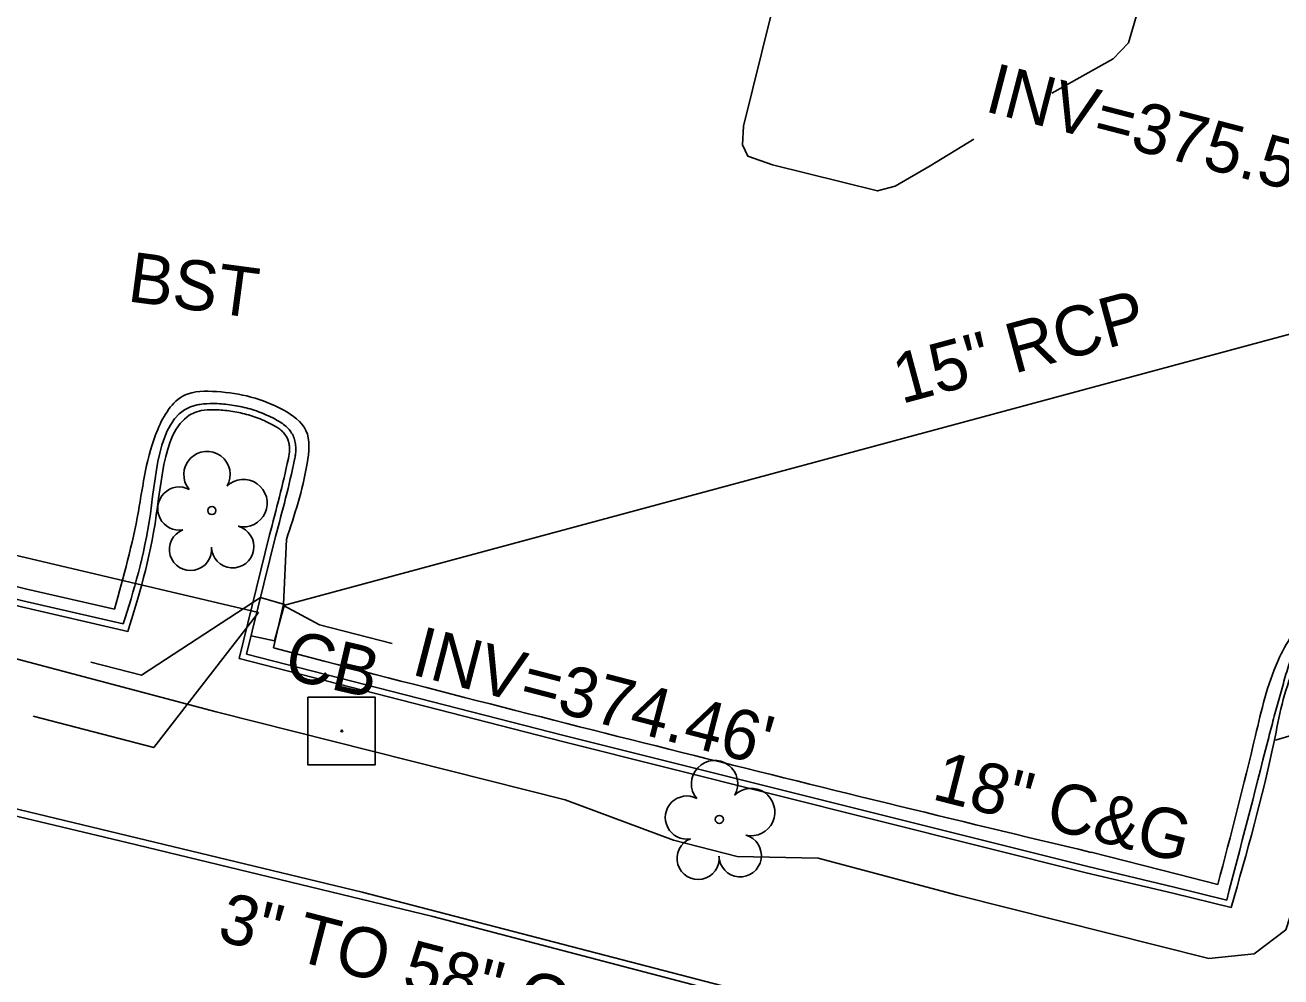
# Model space of a CAD drawing. Extents: x 2089016 to 2094354, y 862840 to 864725.
# Drawn here: x 2092662.4 to 2092763, y 863705 to 863781.3 of the extents above; entities that cross this region are included whole.
import ezdxf

# ---------------------------------------------------------------- set-up
doc = ezdxf.new("R2010")
doc.units = 0
for name, color, linetype in [('Exist Building', 7, 'Continuous'), ('Exist Building Text', 7, 'Continuous'), ('Exist Other Culture Fence Line', 7, 'Continuous'), ('Exist Roads Curbs', 7, 'Continuous'), ('Exist Roads Curbs Text', 7, 'Continuous'), ('Exist Roads EOP', 7, 'Continuous'), ('Exist Roads EOP Other', 7, 'Continuous'), ('Exist Roads EOP Other Text', 7, 'Continuous'), ('Exist Structure Minor Catch Basin Text', 7, 'Continuous'), ('Exist Structure Minor Drop Inlet', 7, 'Continuous'), ('Exist Structure Minor Drop Inlet Leader', 7, 'Continuous'), ('Exist Structure Minor Pipes RCP 15 Inch', 7, 'Continuous'), ('Exist Structure Minor Pipes RCP 15 Inch Invert', 7, 'Continuous'), ('Exist Structure Minor Pipes RCP 15 Inch Leader', 7, 'Continuous'), ('Exist Structure Minor Pipes RCP 15 Inch Text', 7, 'Continuous'), ('Exist Utilities Other Pole With Base CELL', 7, 'Continuous'), ('Exist Vegetation Hedge Row', 7, 'Continuous'), ('Exist Vegetation Tree CELL', 7, 'Continuous')]:
    doc.layers.add(name, color=color, linetype=linetype)

msp = doc.modelspace()

# ---------------------------------------------------------------- linework, layer by layer
at = {"layer": 'Exist Building'}
for p, q in [((2092670.55, 863715.8), (2092651.63, 863720.29)), ((2092695.06, 863709.86), (2092670.55, 863715.8)), ((2092719.12, 863703.57), (2092695.06, 863709.86))]:
    msp.add_line(p, q, dxfattribs=at)
at = {"layer": 'Exist Other Culture Fence Line'}
msp.add_lwpolyline([(2092811.78, 863734.58), (2092806.76, 863722.98), (2092803.58, 863716.36), (2092801.54, 863712.92), (2092798.77, 863709.38), (2092795.98, 863706.58), (2092790.64, 863701.95), (2092785.5, 863698.59), (2092780.3, 863696.17), (2092775.15, 863694.37), (2092768.83, 863693.52), (2092762.71, 863693.79), (2092750.99, 863695.98), (2092726.3, 863702.22), (2092689.4, 863711.81), (2092651.09, 863721.05), (2092618.36, 863728.9), (2092604.89, 863733.06), (2092585.02, 863756.31)], dxfattribs=at)
at = {"layer": 'Exist Roads Curbs'}
for p, q in [((2092679.54, 863730.55), (2092681.98, 863740.45)), ((2092680.15, 863730.91), (2092682.46, 863740.33)), ((2092705.57, 863724.38), (2092680.15, 863730.91)), ((2092705.45, 863723.89), (2092679.54, 863730.55)), ((2092747.43, 863713.38), (2092705.45, 863723.89)), ((2092747.55, 863713.87), (2092705.57, 863724.38)), ((2092754.49, 863712.21), (2092758.69, 863711.17))]:
    msp.add_line(p, q, dxfattribs=at)
for points in [[(2092744.69, 863775.86), (2092749.6, 863778.62), (2092750.83, 863779.91), (2092751.77, 863783.19), (2092756.78, 863802.38), (2092756.98, 863804.25), (2092756.46, 863805.43), (2092755.72, 863805.88), (2092742.47, 863809.01), (2092744.3, 863816.53)], [(2092722.89, 863785), (2092719.96, 863773.22), (2092719.89, 863771.71), (2092720.31, 863770.82), (2092722.3, 863770.11), (2092730.7, 863768.03), (2092732.12, 863768.41), (2092734.92, 863770.04), (2092738.43, 863772.18)], [(2092670.62, 863732.71), (2092662.11, 863734.68), (2092652.85, 863736.97)], [(2092670.26, 863733.32), (2092662.22, 863735.16), (2092652.97, 863737.45)], [(2092754.49, 863712.21), (2092747.55, 863713.87)], [(2092759.05, 863710.6), (2092754.37, 863711.73), (2092747.43, 863713.38)]]:
    msp.add_lwpolyline(points, dxfattribs=at)
for points in [[(2092682.46, 863740.33), (2092683.99, 863746.49), (2092684.06, 863746.88), (2092684.08, 863747.08), (2092684.09, 863747.28), (2092684.06, 863747.73), (2092683.95, 863748.21), (2092683.48, 863748.98), (2092683.11, 863749.31), (2092682.71, 863749.57), (2092681.41, 863750.21), (2092680.1, 863750.64), (2092678.79, 863750.89), (2092677.46, 863750.99), (2092676.43, 863750.92), (2092676.19, 863750.88), (2092672.43, 863742.15), (2092670.26, 863733.32)], [(2092681.98, 863740.45), (2092683.49, 863746.58), (2092683.59, 863747.3), (2092683.56, 863747.66), (2092683.48, 863748.02), (2092683.1, 863748.66), (2092682.81, 863748.92), (2092682.47, 863749.14), (2092681.22, 863749.75), (2092679.98, 863750.16), (2092678.72, 863750.4), (2092677.46, 863750.49), (2092676.51, 863750.42), (2092672.91, 863742.03), (2092670.62, 863732.71)], [(2092787.76, 863728.65), (2092779.29, 863730.7), (2092777.51, 863731.17), (2092775.74, 863731.64), (2092773.97, 863732.11), (2092772.2, 863732.58), (2092771.36, 863732.81), (2092770.53, 863733.05), (2092769.7, 863733.28), (2092768.87, 863733.51), (2092768.49, 863733.59), (2092768.11, 863733.62), (2092767.35, 863733.52), (2092766.58, 863733.26), (2092766.2, 863733.07), (2092766.01, 863732.95), (2092765.83, 863732.83), (2092765.45, 863732.56), (2092765.09, 863732.27), (2092764.76, 863731.94), (2092764.6, 863731.76), (2092764.45, 863731.58), (2092763.98, 863730.84), (2092763.67, 863730.04), (2092763.23, 863728.54), (2092762.81, 863727.04), (2092762.4, 863725.54), (2092762.01, 863724.03), (2092758.69, 863711.17)], [(2092788.12, 863728.07), (2092779.56, 863730.11), (2092772.07, 863732.1), (2092768.85, 863733), (2092766.11, 863732.39), (2092764.12, 863729.81), (2092762.49, 863723.9), (2092759.05, 863710.6)], [(2092530.07, 863721.03), (2092534.33, 863719.65), (2092575.6, 863708.21), (2092621.07, 863695.65), (2092662.26, 863684.12), (2092705.47, 863672.32)], [(2092530.34, 863721.46), (2092534.48, 863720.13), (2092575.73, 863708.69), (2092621.2, 863696.13), (2092662.4, 863684.6), (2092705.61, 863672.81)]]:
    msp.add_spline(points, degree=3, dxfattribs=at)
at = {"layer": 'Exist Roads EOP'}
for points in [[(2092682.29, 863731.41), (2092683.1, 863734.91), (2092683.33, 863740.1)], [(2092669.57, 863734.5), (2092662.54, 863736.11), (2092653.24, 863738.45)], [(2092757.98, 863712.44), (2092754.75, 863713.26), (2092747.83, 863715.02)]]:
    msp.add_lwpolyline(points, dxfattribs=at)
msp.add_ellipse((2093446.69, 866647.98), major_axis=(-2241.79, -2016.35), ratio=0.999899, start_param=0.582015, end_param=0.604423, dxfattribs=at)
for points in [[(2092351.39, 863867.42), (2092346.28, 863853.71), (2092340.44, 863838.83), (2092338.02, 863832.45), (2092326.59, 863809.54), (2092324.18, 863804.42), (2092322.34, 863798.11), (2092322.21, 863794.63), (2092323.26, 863788.18), (2092325.31, 863783.21), (2092329.49, 863777.7), (2092333.36, 863774.11), (2092338.14, 863771.94), (2092365.19, 863764.36), (2092404.76, 863753.49), (2092444.45, 863742.49), (2092470.82, 863735.23), (2092515.55, 863722.74), (2092529.36, 863718.89), (2092533.92, 863717.65), (2092575.11, 863706.35), (2092620.49, 863693.63), (2092661.52, 863682.27), (2092704.83, 863670.36)], [(2092683.33, 863740.1), (2092685, 863746.18), (2092684.9, 863748.83), (2092683.08, 863750.47), (2092677.74, 863751.94), (2092675.17, 863751.65), (2092673.02, 863748.9), (2092671.47, 863742.32), (2092669.57, 863734.5)], [(2092787.17, 863729.78), (2092780.94, 863731.2), (2092772.37, 863733.46), (2092769.24, 863734.33), (2092765.5, 863733.83), (2092762.81, 863730.4), (2092761, 863724.37), (2092757.98, 863712.44)], [(2092828.1, 863729.19), (2092826.25, 863724.52), (2092817.36, 863700.95), (2092813.46, 863691.03), (2092810.42, 863683.66), (2092808.15, 863679.13), (2092808.17, 863679.13), (2092804.47, 863673.86), (2092801.41, 863670.18), (2092796.05, 863666.12), (2092792.79, 863663.98), (2092786.45, 863660.55), (2092777.32, 863657), (2092767.89, 863655.43), (2092759.35, 863655.78), (2092746.24, 863658.87)], [(2092733.96, 863624.56), (2092729.42, 863627.24), (2092710.26, 863638.22), (2092685.56, 863646.14), (2092644.34, 863656.7), (2092636.3, 863658.85), (2092633.44, 863659.08), (2092631.45, 863657.89), (2092628.59, 863656.45), (2092626.77, 863655.79), (2092624.31, 863656.27), (2092613.98, 863659.23), (2092588.53, 863665.82), (2092584.48, 863666.74), (2092582.65, 863668.4), (2092580.87, 863671.65), (2092573.74, 863674.74), (2092530.78, 863685.35), (2092492.66, 863694.32), (2092471.57, 863699.61), (2092432.29, 863709.14), (2092390.23, 863719.97)]]:
    msp.add_spline(points, degree=3, dxfattribs=at)
at = {"layer": 'Exist Roads EOP Other'}
msp.add_lwpolyline([(2092806.46, 863743.02), (2092795.1, 863718.03), (2092770.9, 863724.24), (2092766.95, 863725.31), (2092762.59, 863724)], dxfattribs=at)
for points in [[(2092744.83, 863669.14), (2092739.53, 863670.51), (2092698.61, 863681.9), (2092655.56, 863693.83), (2092614.88, 863705.04), (2092572.51, 863716.82), (2092534.25, 863727.26), (2092490.85, 863739.3), (2092453.11, 863749.73), (2092413.17, 863760.74), (2092373.71, 863771.76), (2092342.37, 863780.54), (2092336.27, 863784.25), (2092333.6, 863789.3), (2092333.19, 863795.1), (2092333.89, 863798.65), (2092336.05, 863803.25), (2092354.66, 863838.72)], [(2092743.53, 863664.36), (2092738.18, 863665.86), (2092697.44, 863677.09), (2092654.51, 863689.14), (2092613.57, 863700.33), (2092571.3, 863712.05), (2092533.04, 863722.78), (2092489.78, 863734.76), (2092451.86, 863745.14), (2092412.17, 863756.14), (2092372.39, 863767.04), (2092340.78, 863775.86), (2092336.36, 863777.72), (2092332.77, 863780.97)], [(2092744.81, 863668.98), (2092750.12, 863667.66), (2092760.64, 863665.3), (2092769.92, 863665.38), (2092774.61, 863666.3), (2092783.29, 863669.98), (2092790.76, 863673.98), (2092797.37, 863680.05), (2092800.1, 863684.1), (2092802.17, 863688.67), (2092813.02, 863716.3)]]:
    msp.add_spline(points, degree=3, dxfattribs=at)
at = {"layer": 'Exist Structure Minor Drop Inlet'}
msp.add_lwpolyline([(2092680.52, 863732.37), (2092682.39, 863731.96), (2092683.18, 863734.89), (2092681.25, 863735.44)], dxfattribs=at)
at = {"layer": 'Exist Structure Minor Drop Inlet Leader'}
msp.add_lwpolyline([(2092681.25, 863735.44), (2092671.73, 863729.21), (2092667.67, 863730.26)], dxfattribs=at)
at = {"layer": 'Exist Structure Minor Pipes RCP 15 Inch'}
for p, q in [((2092683.11, 863734.8), (2092796.12, 863765.27)), ((2092681.1, 863734.24), (2092611.29, 863750.66))]:
    msp.add_line(p, q, dxfattribs=at)
at = {"layer": 'Exist Structure Minor Pipes RCP 15 Inch Leader'}
for points in [[(2092681.1, 863734.24), (2092672.71, 863723.41), (2092663.03, 863725.92)], [(2092683.11, 863734.8), (2092685.99, 863733.25), (2092691.8, 863731.74)]]:
    msp.add_lwpolyline(points, dxfattribs=at)
at = {"layer": 'Exist Utilities Other Pole With Base CELL'}
msp.add_line((2092687.78, 863724.74), (2092687.78, 863724.74), dxfattribs=at)
msp.add_lwpolyline([(2092685.05, 863727.44), (2092690.45, 863727.44), (2092690.45, 863722.04), (2092685.05, 863722.04), (2092685.05, 863727.44)], dxfattribs=at)
msp.add_circle((2092687.78, 863724.74), 0.0707, dxfattribs=at)
at = {"layer": 'Exist Vegetation Hedge Row'}
msp.add_lwpolyline([(2092795.1, 863717.96), (2092793.95, 863715.41), (2092792.21, 863714.05), (2092786.64, 863714.73), (2092775.24, 863717.79), (2092769.97, 863719.67), (2092768.27, 863720.15), (2092766.64, 863718.42), (2092764.77, 863712.92), (2092763.43, 863708.81), (2092760.89, 863706.87), (2092757.26, 863706.5), (2092737.08, 863711.57), (2092725.96, 863714.56), (2092719.46, 863714.68), (2092714.36, 863715.98), (2092705.68, 863719.21), (2092677.7, 863726.28), (2092654.71, 863732.38)], dxfattribs=at)
at = {"layer": 'Exist Vegetation Tree CELL'}
for p, q in [((2092677.36, 863742.41), (2092677.36, 863742.41)), ((2092718.03, 863717.65), (2092718.03, 863717.65))]:
    msp.add_line(p, q, dxfattribs=at)
for centre in [(2092677.36, 863742.41), (2092718.03, 863717.65)]:
    msp.add_circle(centre, 0.326, dxfattribs=at)
for centre, radius, start, end in [((2092676.97, 863745.29), 1.86, 330.1651, 219.7134), ((2092674.75, 863742.57), 1.73, 62.6636, 279.3457), ((2092679.9, 863743), 1.9, 257.1011, 134.1999), ((2092679.03, 863739.51), 1.7, 181.2822, 74.56), ((2092675.65, 863739.29), 1.69, 111.5671, 6.231), ((2092717.65, 863720.52), 1.86, 330.1651, 219.7134), ((2092720.58, 863718.24), 1.9, 257.1011, 134.1999), ((2092715.43, 863717.8), 1.73, 62.6636, 279.3457), ((2092716.33, 863714.53), 1.69, 111.5671, 6.231), ((2092719.7, 863714.75), 1.7, 181.2822, 74.56)]:
    msp.add_arc(centre, radius, start, end, dxfattribs=at)

# ---------------------------------------------------------------- texts
at = {"layer": 'Exist Building Text'}
msp.add_text('3" TO 58" CONC WALL', height=4, rotation=345.4987, dxfattribs=at).set_placement((2092677.68, 863708))
at = {"layer": 'Exist Roads Curbs Text'}
msp.add_text('18" C&G', height=4, rotation=345.7128, dxfattribs=at).set_placement((2092734.96, 863719.3))
at = {"layer": 'Exist Roads EOP Other Text'}
msp.add_text('BST', height=4, rotation=352.4157, dxfattribs=at).set_placement((2092670.51, 863759.19))
at = {"layer": 'Exist Structure Minor Catch Basin Text'}
msp.add_text('CB', height=4, rotation=346.8592, dxfattribs=at).set_placement((2092682.99, 863729.01))
at = {"layer": 'Exist Structure Minor Pipes RCP 15 Inch Invert'}
for s, p in [("INV=375.59'", (2092739.18, 863774.44)), ("INV=374.46'", (2092693.23, 863729.3))]:
    msp.add_text(s, height=4, rotation=345.4489, dxfattribs=at).set_placement(p)
at = {"layer": 'Exist Structure Minor Pipes RCP 15 Inch Text'}
msp.add_text('15" RCP', height=4, rotation=15.0881, dxfattribs=at).set_placement((2092732.62, 863750.94))

doc.saveas('drawing.dxf')
